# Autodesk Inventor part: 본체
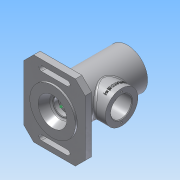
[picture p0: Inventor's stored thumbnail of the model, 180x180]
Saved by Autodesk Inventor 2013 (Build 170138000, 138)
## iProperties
Created: 2017-10
Part Number: 본체
Material: 알루미늄 6061
Document SubType Name: Modeling
Designer: Administrator
Density: 2.71 g/cm^3
Mass: 840.307 g
Surface Area: 700.57 cm^2
Volume: 310.076 cm^3
Author: Administrator
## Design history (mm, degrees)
sketch "스케치1"
  geometry: C1 r 31 at (0, 0); 1 further point
  constraints: 1 centre point, 1 coincident
  dimensions: "d0" = 62 diameter of C1
extrude "돌출1" new body sketch "스케치1" distance "d1" = 102; taper "d2" = 0 deg
node "작업 평면1"
sketch "스케치2"
  geometry: L1 (102, -31)-(102, 31) reference; C1 r 25 at (46, 0); 1 further point
  constraints: 1 centre point, 1 horizontal alignment
  dimensions: "d4" = 50 diameter of C1; "d5" = 56 distance from line of L1 C1.centre
extrude "돌출2" join sketch "스케치2" stored distance "d6" = 102; taper "d7" = 0 deg
sketch "스케치4"
  geometry: L1 (47, 58)-(-47, 58); L2 (-47, 58)-(-47, -58); L3 (-47, -58)-(47, -58); L4 (47, -58)-(47, 58); C1 r 31 at (0, 0) reference; 1 further point
  constraints: 8 end point, 2 parallel, 1 horizontal, 1 horizontal alignment, 1 midpoint, 1 perpendicular
  dimensions: "d10" = 116 distance of L1.end L2.end; "d12" = 47 distance of point (-47, 0) C1.centre; "d13" = 94 distance of L1.start L1.end
extrude "돌출3" join sketch "스케치4" distance "d14" = 10; taper "d15" = 0 deg
sketch "스케치5"
  geometry: C1 r 35 at (0, 0); 1 further point
  constraints: 1 centre point, 1 coincident
  dimensions: "d16" = 70 diameter of C1
extrude "돌출4" join sketch "스케치5" distance "d18" = 3; taper "d19" = 0 deg
hole "구멍1" diameter "d22" = 40.376; stored, may be unused: countersink angle "d26" = 90 deg, drill point angle "d28" = 0 deg; dims "d20" = 10, "d21" = 10, "d23" = 6, "d24" = 4, "d25" = 2, "d27" = 9
sketch "스케치6"
  geometry: C1 r 20.188 at (0, 0) reference; 1 further point
  constraints: 1 coincident
hole "구멍2" sketch "스케치6" at (0, 0) diameter "d29" = 40; stored, may be unused: countersink angle "d33" = 90 deg, drill point angle "d35" = 0 deg; dims "d30" = 6, "d31" = 48, "d32" = 3, "d34" = 12
sketch "스케치7"
  geometry: C1 r 20 at (0, 0) reference; C2 r 17.5 at (0, 0)
  constraints: 1 centre point, 1 coincident
  dimensions: "d36" = 35 diameter of C2
extrude "돌출5" cut sketch "스케치7" distance "d37" = 3.25; taper "d38" = 0 deg
sketch "스케치8"
  geometry: C1 r 17.5 at (0, 0) reference; 1 further point
  constraints: 1 coincident
hole "구멍3" sketch "스케치8" at (0, 0) diameter "d39" = 35; stored, may be unused: countersink angle "d43" = 90 deg, drill point angle "d45" = 0 deg; dims "d40" = 6, "d41" = 37, "d42" = 1.75, "d44" = 12.75
sketch "스케치9"
  geometry: C1 r 17.5 at (0, 0) reference; 1 further point
  constraints: 1 coincident
hole "구멍4" sketch "스케치9" at (0, 0) diameter "d46" = 35; stored, may be unused: countersink angle "d50" = 90 deg, drill point angle "d52" = 0 deg; dims "d47" = 6, "d48" = 52, "d49" = 38, "d51" = 49
sketch "스케치11"
  geometry: C1 r 17.5 at (0, 0) reference; 1 further point
  constraints: 1 coincident
hole "구멍5" sketch "스케치11" at (0, 0) diameter "d53" = 20; stored, may be unused: countersink angle "d57" = 90 deg, drill point angle "d59" = 0 deg; dims "d54" = 6, "d55" = 33, "d56" = 5, "d58" = 15
sketch "스케치14"
  geometry: L1 (-13, 35)-(-13, -35) reference; L2 (-13, 0)-(-13, 22); L3 (-13, 22)-(1, 16); L4 (1, 16)-(1, 0); L5 (1, 0)-(-13, 0)
  constraints: 8 end point, 1 midpoint, 1 parallel, 1 perpendicular, 1 point on line
  dimensions: "d70" = 22 distance of L2.start L2.end; "d71" = 16 distance of L3.end L4.end; "d72" = 14 distance of L4.end L2.start
revolve "회전1" sketch "스케치14" stored, may be unused: angle "d73" = 90 deg
sketch "스케치16"
  geometry: L1 (1, 16)-(1, -16) reference; L2 (1, 0)-(1, 12.5); L3 (1, 12.5)-(8.3, 12.5); L4 (8.3, 12.5)-(8.3, 10); L5 (8.3, 10)-(11, 10); L6 (11, 10)-(11, 0); L7 (11, 0)-(1, 0); 1 further point
  constraints: 12 end point, 3 perpendicular, 2 parallel, 1 midpoint, 1 point on line
  dimensions: "d74" = 12.5 distance of L2.start L2.end; "d75" = 7.3 distance of L2.end L3.end; "d76" = 10 distance of L5.end L6.end; "d77" = 2.7 distance of L4.end L5.end
revolve "회전2" sketch "스케치16" stored, may be unused: angle "d78" = 90 deg
sketch "스케치17"
  geometry: 1 further point
sketch "스케치18"
  geometry: 1 further point
sketch "스케치19"
  geometry: L1 (-47, -58)-(-47, 58) reference; L2 (20, 50)-(-20, 50); L3 (20, 42)-(-20, 42); C1 r 31 at (0, 0) reference; A1 r 4 centre (20, 46) between (20, 42) and (20, 50); A2 r 4 centre (-20, 46) between (-20, 50) and (-20, 42)
  constraints: 4 end point, 4 point on circle, 2 centre point, 2 parallel, 2 tangent, 1 equal radius, 1 perpendicular
  dimensions: "d79" = 40 distance of A2.centre A1.centre; "d81" = 4 radius of A1; "d82" = 46 vertical distance of C1.centre A2.centre; "d83" = 20 horizontal distance of C1.centre A2.centre
extrude "돌출6" cut sketch "스케치19" stored distance "d84" = 14; taper "d85" = 0 deg
sketch "스케치21"
  geometry: C1 r 25 at (0, 0) reference; A1 r 20.5 centre (0, 0) between (20.5, 0) and (-20.5, 0); 1 further point
  constraints: 2 horizontal alignment, 2 point on circle, 1 centre point, 1 coincident
  dimensions: "d86" = 41 diameter of A1
hole "구멍6" sketch "스케치21" at (20.5, 0), (-20.5, 0) diameter "d87" = 2.459; stored, may be unused: countersink angle "d91" = 90 deg, drill point angle "d93" = 118 deg; dims "d88" = 6, "d89" = 44, "d90" = 5, "d92" = 8
hole "구멍7" diameter "d96" = 32; stored, may be unused: countersink angle "d100" = 90 deg, drill point angle "d102" = 0 deg; dims "d94" = 10, "d95" = 10, "d97" = 6, "d98" = 44, "d99" = 5, "d101" = 40
chamfer "모따기1" distance "d104" = 1; stored, may be unused: second distance "d105" = 2, angle "d106" = 45 deg
chamfer "모따기2" distance "d107" = 1; stored, may be unused: second distance "d108" = 2, angle "d109" = 30 deg
chamfer "모따기3" distance "d110" = 1; stored, may be unused: second distance "d111" = 2, angle "d112" = 30 deg
fillet "모깎기2" dims "d113" = 3
chamfer "모따기4" distance "d114" = 1; stored, may be unused: second distance "d115" = 2, angle "d116" = 30 deg
node "작업 평면2"
sketch "스케치23"
  geometry: L1 (47, 71)-(47, 21) reference; L2 (31, 102)-(-31, 102) reference; 2 further points
  constraints: 1 other
  dimensions: "d118" = 10 distance from line of L1 point (37, 46); "d119" = 56 distance from line of L2 point (37, 46)
feature "엠보싱1" sketch "스케치23" dims "d0" = 62, "d120" = 0.5, "d121" = 0
chamfer "모따기5" distance "d122" = 15; stored, may be unused: second distance "d123" = 2, angle "d124" = 30 deg
chamfer "모따기6" distance "d125" = 1; stored, may be unused: second distance "d126" = 2, angle "d127" = 30 deg
fillet "모깎기3" dims "d128" = 0.3
fillet "모깎기4" dims "d129" = 3
fillet "모깎기6" dims "d131" = 3
fillet "모깎기7" dims "d132" = 0.3
node "솔리드1"
mirror "대칭1"
other parameters: "d3" = 47, "d117" = 148
